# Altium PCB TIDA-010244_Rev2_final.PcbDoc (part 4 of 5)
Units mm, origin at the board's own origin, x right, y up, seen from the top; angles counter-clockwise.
Board outline 155.23 x 187.6 mm, 4 copper layers (GND/Signal 1, Solid GND Layer 1, Solid Power Layer 1, GND/Signal Layer 2), stack 1.59 mm thick; 350 components, 237 nets, 1153 pads, 380 vias.
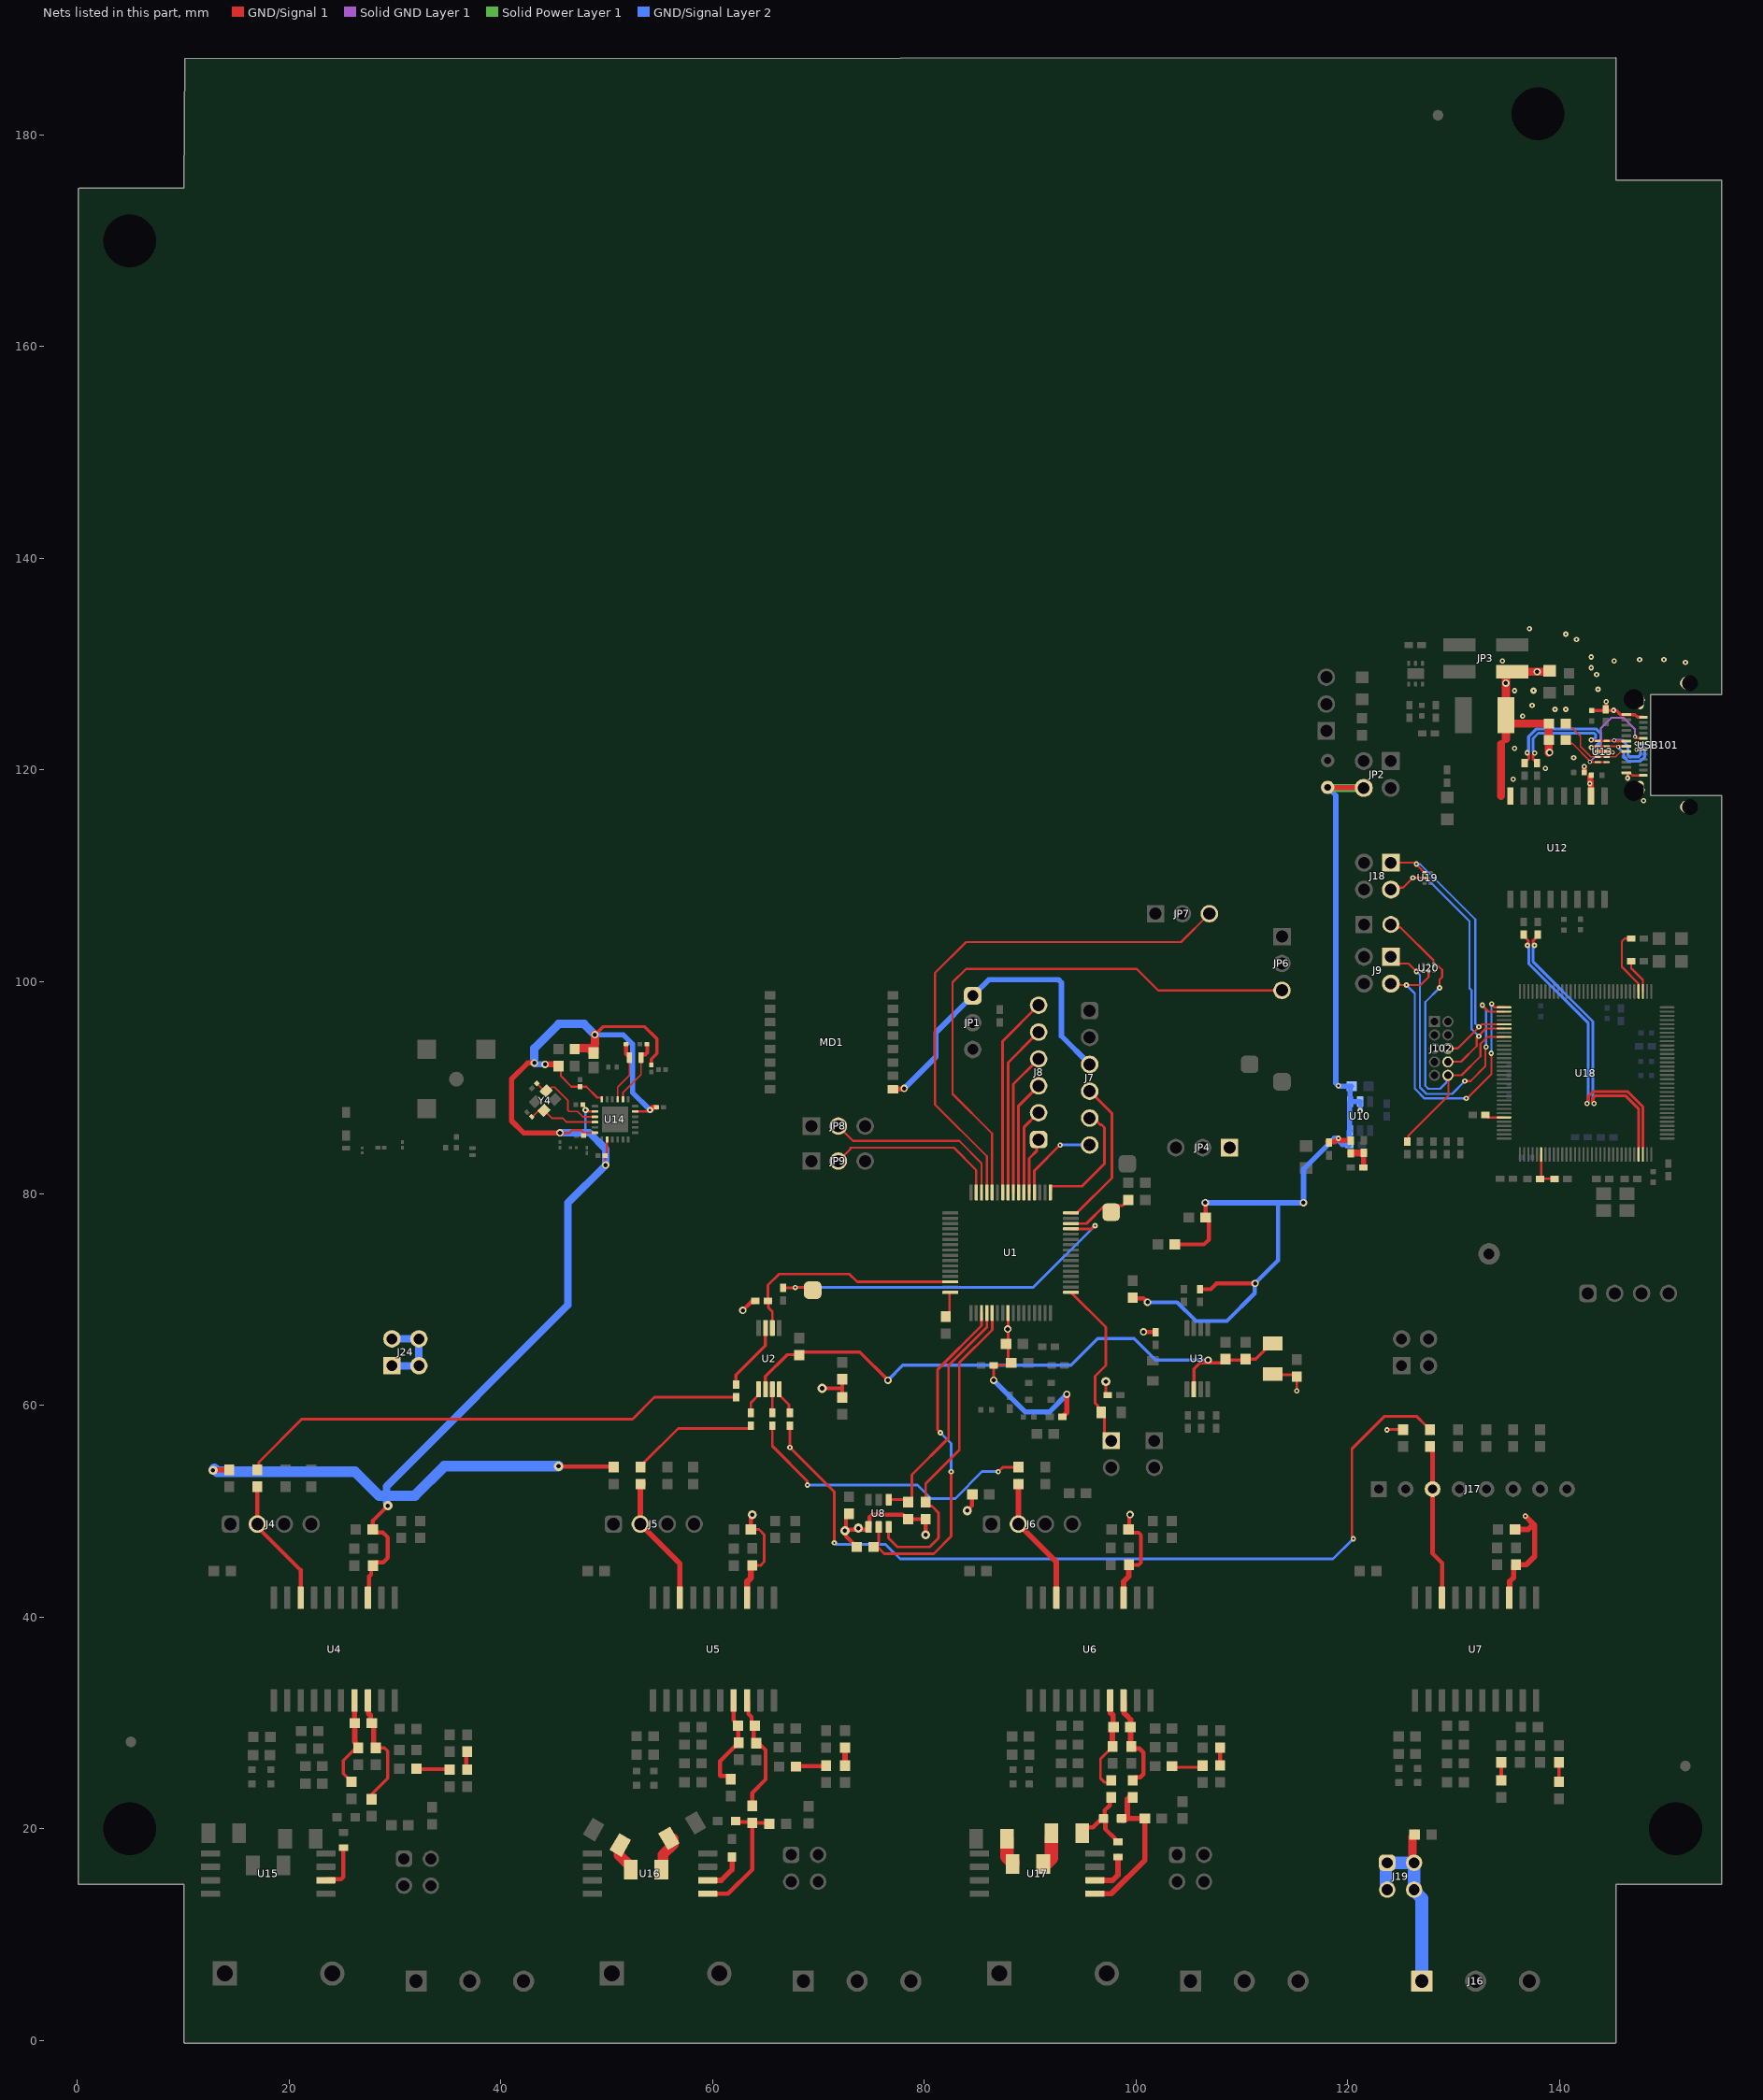
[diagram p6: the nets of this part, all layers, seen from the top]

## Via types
v1: diameter 0.5, hole 0.2, GND/Signal 1 to GND/Signal Layer 2, tented both sides, 236 vias
v2: diameter 0.5, hole 0.2, GND/Signal 1 to GND/Signal Layer 2, 46 vias
v3: diameter 0.864, hole 0.406, GND/Signal 1 to GND/Signal Layer 2, 41 vias
v4: diameter 0.7, hole 0.4, GND/Signal 1 to GND/Signal Layer 2, tented both sides, 40 vias
v5: diameter 0.61, hole 0.203, GND/Signal 1 to GND/Signal Layer 2, tented both sides, 10 vias
v6: diameter 0.4, hole 0.2, GND/Signal 1 to GND/Signal Layer 2, tented both sides, 7 vias

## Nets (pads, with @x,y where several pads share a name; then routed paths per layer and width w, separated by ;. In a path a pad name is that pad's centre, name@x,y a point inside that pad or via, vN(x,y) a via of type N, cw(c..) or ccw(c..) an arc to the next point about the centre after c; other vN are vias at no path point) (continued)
NetR63_1: R63.1 R67.1 R101.2 U16.5 | length 13
  GND/Signal 1 w0.381: U16.5@59.552,13.843 61.468,13.843 63.754,16.129 R67.1@63.754,20.536 ; R63.1@62.191,20.701 62.211,20.682 62.211,20.619 R67.1@63.671,20.619 ; R67.1@63.754,20.574 R67.1@63.754,20.536 ; R101.2@65.374,20.536 R67.1@63.754,20.536 ; R101.2@65.397,20.574 R101.2@65.621,20.574
NetR64_1: R64.1 R65.2 | length 3.1
  GND/Signal 1 w1.016: R64.1@51.435,18.669 51.184,18.418 51.184,17.491 52.271,16.404 R65.2@52.271,16.129
NetR65_1: R65.1 R66.2 | length 3.5
  GND/Signal 1 w1: R65.1@55.171,16.129 55.321,16.279 55.321,17.527 56.318,18.524 56.318,19.044 R66.2@56.275,19.087
NetR68_1: R68.1 R69.2 R72.1 R127.1 | length 7.5
  GND/Signal 1 w0.406: R72.1@94.922,19.558 94.922,19.678 95.369,20.125 95.944,20.125 R69.2@96.647,20.828 ; R69.2@97.028,21.082 97.112,20.998 97.112,19.945 98.051,19.006 98.051,18.881 98.173,18.759 R127.1@98.298,18.759 ; R69.2@97.037,21.082 97.037,21.726 97.515,22.204 97.515,23.093 R68.1@97.536,23.114
NetR69_1: R69.1 R73.1 R103.2 U17.5 | length 14.3
  GND/Signal 1 w0.508: U17.5@96.117,13.843 97.663,13.843 100.838,17.018 R103.2@100.838,20.955 99.187,20.955 99.124,20.892 ; R69.1@98.64,20.955 R69.1@98.787,20.809 ; R69.1@98.933,20.955 99.187,21.209 99.187,22.797 99.441,23.051 R73.1@99.441,23.076
NetR70_1: R70.1 R71.2 | length 2.5
  GND/Signal 1 w1.27: R70.1@87.81,19.05 87.825,19.035 87.825,17.331 R71.2@88.392,16.764
NetR71_1: R71.1 R72.2 | length 2.6
  GND/Signal 1 w1.27: R71.1@91.567,16.764 92.007,17.204 R72.2@92.007,19.162
NetR74_2: R74.2 R75.1 | length 1.9
  GND/Signal 1 w0.381: R75.1@36.703,27.432 36.74,27.395 36.74,25.649 R74.2@36.777,25.612 ; R74.2@36.83,25.565 R74.2@36.872,25.607
NetR76_2: R76.2 R77.1 | length 3.3
  GND/Signal 1 w0.381: R77.1@32.042,25.654 32.087,25.609 35.224,25.609 R76.2@35.306,25.527
NetR78_2: R78.2 R79.1 | length 1.7
  GND/Signal 1 w0.508: R78.2@72.517,25.946 R79.1@72.517,27.648 R79.1@72.517,27.686
NetR80_2: R80.2 R81.1 | length 2.6
  GND/Signal 1 w0.381: R81.1@67.893,25.856 67.938,25.901 70.478,25.901 R80.2@70.485,25.908
NetR82_2: R82.2 R83.1 | length 1.8
  GND/Signal 1 w0.381: R82.2@107.95,25.971 107.95,27.432 R83.1@108.204,27.686
NetR84_2: R84.2 R85.1 | length 3
  GND/Signal 1 w0.254: R85.1@103.302,25.885 103.422,25.765 R85.1@103.655,25.532 ; R85.1@103.422,25.797 103.438,25.781 R84.2@105.918,25.781
NetR92_2: R92.2 R93.1 | length 1.9
  GND/Signal 1 w0.35: R92.2@134.366,24.384 134.493,24.511 R92.2@134.493,24.549 R93.1@134.493,26.251
NetR94_2: R94.2 R95.1 | length 1.9
  GND/Signal 1 w0.35: R94.2@139.827,24.384 139.954,24.511 R95.1@139.954,26.251
NetR119_2: R119.2 U18.3 | length 3.3
  GND/Signal 1 w0.2: R119.2@146.771,101.93 146.771,101.273 147.869,100.175 U18.3@147.869,99.084
NetR120_2: R120.2 U18.4 | length 6.4
  GND/Signal 1 w0.2: R120.2@146.771,104.089 146.165,104.089 145.887,103.811 145.887,101.409 147.469,99.827 U18.4@147.469,99.084
NetR121_1: R121.1 R124.2 U18.70 | length 3.7
  GND/Signal 1 w0.2: U18.70@138.269,83.684 138.269,81.481 R121.1@138.169,81.381 R124.2@139.548,81.381
NetR123_2: R123.2 U15.6 | length 4.6
  GND/Signal 1 w0.381: U15.6@23.484,15.113 23.593,15.222 24.923,15.222 25.146,15.446 R123.2@25.146,18.288
NetR125_2: R125.2 U16.6 | length 3.9
  GND/Signal 1 w0.5: U16.6@59.552,15.113 60.833,15.113 61.849,16.129 R125.2@61.849,17.311
NetR126_2: R126.2 U18.59 | length 1.9
  GND/Signal 1 w0.2: R126.2@133.008,87.411 133.235,87.184 U18.59@134.769,87.184
NetR127_2: R127.2 U17.6 | length 4.2
  GND/Signal 1 w0.508: U17.6@96.117,15.113 97.79,15.113 98.298,15.621 R127.2@98.298,17.38
NEUTRAL: J16.1 J19.1 J19.2 J19.3 J19.4 R106.2 | length 19.2
  GND/Signal 1 w0.762: J19.3@126.111,16.637 126.119,16.645 126.119,17.478 126.111,17.486 126.111,19.24 126.365,19.494 R106.2@126.365,19.525
  GND/Signal Layer 2 w1.2: J19.1@123.571,16.51 123.634,16.447 123.634,14.326 J19.2@123.73,14.23 ; J19.1@123.946,16.77 J19.3@126.27,16.77 ; J19.4@126.238,14.167 127,13.405 J16.1@127,5.588 ; J19.3@126.238,16.891 126.27,16.859 J19.3@126.27,16.77 ; J19.4@126.27,14.23 J19.3@126.27,16.77
PA12: J8.1 U1.5 | length 5.3
  GND/Signal 1 w0.254: U1.5@89.916,80.107 89.916,83.312 90.637,84.033 90.637,84.668 J8.1@90.932,84.963
PA13: J8.2 U1.6 | length 8.2
  GND/Signal 1 w0.254: U1.6@89.416,80.107 89.416,86.241 90.678,87.503 J8.2@90.678,87.757
PA14: J8.3 U1.7 | length 10.7
  GND/Signal 1 w0.254: U1.7@88.916,80.107 88.916,88.281 90.551,89.916 J8.3@90.805,89.916
PA15: J8.4 U1.8 | length 13.2
  GND/Signal 1 w0.254: U1.8@88.416,80.107 88.416,90.321 J8.4@90.551,92.456
PA16: J8.5 U1.9 | length 16.6
  GND/Signal 1 w0.254: U1.9@87.916,80.107 87.916,92.361 90.424,94.869 J8.5@91.186,94.869
PA17: J8.6 U1.10 | length 19.2
  GND/Signal 1 w0.254: U1.10@87.416,80.107 87.416,94.401 J8.6@90.805,97.79 J8.6@90.805,97.917
PWM: pad.3@97.663,78.232 R19.1 U1.62 | length 6.3
  GND/Signal 1 w0.254: U1.62@93.866,77.157 95.318,77.157 97.028,78.867 98.754,78.867 98.903,79.016 98.903,79.027 99.251,79.375 R19.1@99.276,79.375
REACT: D2.1 J3.1 U1.49 | length 16.7
  GND/Signal 1 w0.254: U1.49@93.866,70.657 94.225,70.657 U1.49@94.248,70.634 ; U1.49@93.912,70.611 97.155,67.368 97.155,63.754 96.139,62.738 96.139,60.198 96.39,59.947 96.39,59.632 97.036,58.986 97.036,56.634 J3.1@97.155,56.515
RTS_FTDI: J7.6 U1.4 | length 8.3
  GND/Signal 1 w0.254: U1.4@90.416,80.107 90.416,82.161 v1@92.835,84.58
  GND/Signal Layer 2 w0.254: v1(92.837,84.582) 95.504,84.582 J7.6@95.584,84.662
RXD_FTDI: J7.5 U1.1 | length 11.3
  GND/Signal 1 w0.254: U1.1@91.916,80.107 91.916,80.241 91.939,80.264 91.939,80.68 94.904,80.68 97.028,82.804 97.028,86.233 96.765,86.496 96.635,86.496 96.266,86.865 J7.5@96.266,87.122
SPI_CLK_1: R12.2 R28.2 | length 48.4
  GND/Signal 1 w0.254: R28.2@17.018,53.886 17.153,54.021 17.153,54.618 21.209,58.674 52.451,58.674 54.518,60.741 R12.2@62.23,60.741
SPI_CLK_1_H: J4.2 R28.1 U4.18 | length 12
  GND/Signal 1 w0.381: J4.2@17.018,48.768 R28.1@17.018,52.286 R28.1@17.018,52.324 ; J4.2@17.433,48.675 17.306,48.548 17.306,48.226 21.102,44.43 U4.18@21.102,41.812
SPI_CLK_2: R15.2 R35.2 | length 12.4
  GND/Signal 1 w0.254: R35.2@53.213,54.14 53.561,54.488 53.561,54.607 56.755,57.801 63.454,57.801 63.627,57.974 R15.2@63.627,58.074 R15.2@63.627,58.293
SPI_CLK_2_H: J5.2 R35.1 U5.18 | length 12.2
  GND/Signal 1 w0.508: J5.2@53.188,48.768 53.188,52.299 R35.1@53.467,52.578 ; J5.2@53.34,48.616 56.921,45.034 U5.18@56.921,41.807
SPI_CLK_3: R17.2 R44.2 | length 28.8
  GND/Signal 1 w0.254: R17.2@65.563,58.234 R17.2@65.602,58.194 ; R17.2@65.659,58.074 65.659,56.134 68.959,52.834 68.959,52.453 v1(68.961,52.451) ; v1(86.995,53.721) 87.414,54.14 R44.2@88.9,54.14
  GND/Signal Layer 2 w0.254: v1@68.961,52.473 v1(68.961,52.451) 79.375,52.451 80.645,51.181 82.931,51.181 85.471,53.721 v1(86.995,53.721)
SPI_CLK_3_H: J6.2 R44.1 U6.18 | length 12
  GND/Signal 1 w0.508: R44.1@88.773,52.451 88.9,52.324 J6.2@88.9,48.768 ; J6.2@89.027,48.641 92.481,45.187 U6.18@92.481,41.807
SPI_CLK_4: R13.2 R89.2 | length 81
  GND/Signal 1 w0.254: R13.2@67.31,58.074 v1(67.31,56.007) 71.501,51.816 v1(71.501,46.99) ; v1(120.523,47.371) 120.396,47.498 120.396,55.88 123.444,58.928 126.53,58.928 127.389,58.069 127.414,58.069 127.762,57.721 R89.2@127.762,57.696
  GND/Signal Layer 2 w0.254: v1(71.501,46.99) 71.568,46.99 71.725,46.832 76.358,46.832 77.724,45.466 118.618,45.466 v1(120.523,47.371)
SPI_CLK_4_H: J17.3 R89.1 U7.18 | length 14.2
  GND/Signal 1 w0.406: R89.1@127.889,55.753 128.016,55.626 J17.3@128.016,52.07 ; J17.3@128.016,51.943 128.016,45.974 128.905,45.085 U7.18@128.905,41.807
SPI_CLK_EN: R47.1 U1.30 U2.2 | length 22.2
  GND/Signal 1 w0.254: R47.1@65.243,69.85 65.243,71.339 66.294,72.39 72.927,72.39 73.66,71.657 U1.30@82.466,71.657 ; R47.1@65.278,69.85 65.278,69.215 65.659,68.834 ; U2.2@65.654,67.289 65.654,68.834
SPI_from_Buf_1: R12.1 U2.3 | length 6.5
  GND/Signal 1 w0.305: R12.1@62.23,61.941 62.23,62.865 65.004,65.639 U2.3@65.004,67.289 ; U2.3@65.004,67.289 U2.3@65.024,67.31
SPI_from_Buf_2: R15.1 U2.5 | length 2.5
  GND/Signal 1 w0.254: R15.1@63.754,59.309 63.627,59.436 63.627,60.237 64.354,60.964 U2.5@64.354,61.489
SPI_from_Buf_3: R17.1 U2.7 | length 2.6
  GND/Signal 1 w0.254: R17.1@65.486,59.609 65.486,59.482 R17.1@65.659,59.309 ; U2.7@65.654,61.489 65.656,61.486 65.656,59.439 R17.1@65.786,59.309
SPI_from_Buf_4: R13.1 U2.8 | length 3.1
  GND/Signal 1 w0.254: U2.8@66.304,61.489 66.304,60.964 U2.8@66.35,60.917 ; U2.8@66.35,61.251 U2.8@66.35,60.917 ; R13.1@67.437,59.182 67.213,59.406 67.213,60.055 U2.8@66.35,60.917
SPI_SCK: pad.3@69.469,70.866 R14.1 U1.61 | length 35.9
  GND/Signal 1 w0.254: R14.1@66.675,71.085 v1@67.818,71.085 ; v1(67.818,71.12) pad.3@69.469,71.12 ; U1.61@93.866,76.657 95.767,76.657 96.072,76.962 v1(96.139,76.962)
  GND/Signal Layer 2 w0.254: v1(67.818,71.12) 90.297,71.12 v1(96.139,76.962)
SWCLK: JP7.3 U1.13 | length 51.5
  GND/Signal 1 w0.2: U1.13@85.916,80.107 85.916,83.502 81.026,88.392 81.026,100.838 83.947,103.759 104.267,103.759 JP7.3@106.934,106.426 107.188,106.68 JP7.3@107.315,106.68
SWDIO: JP6.3 U1.12 | length 53.9
  GND/Signal 1 w0.2: U1.12@86.416,80.107 86.416,85.669 82.677,89.408 82.677,99.949 83.947,101.219 100.076,101.219 102.108,99.187 JP6.3@113.792,99.187
TMAG_INT: R98.1 U1.35 U8.5 | length 33.4
  GND/Signal 1 w0.254: R98.1@75.692,46.863 75.349,46.863 76.238,45.974 80.899,45.974 82.55,47.625 v1(82.55,53.721) ; R98.1@75.692,46.99 U8.5@75.692,48.484 ; v1(81.534,57.404) 81.534,57.422 81.28,57.676 81.28,63.373 85.416,67.509 U1.35@85.416,68.707
  GND/Signal Layer 2 w0.254: v1(81.534,57.404) 82.55,56.388 v1(82.55,53.721)
TMAG_SCL: R96.1 U1.36 U8.1 | length 22.9
  GND/Signal 1 w0.254: U8.1@76.642,51.084 78.456,51.084 R96.1@78.594,50.946 ; R96.1@78.676,50.863 78.834,51.021 78.834,53.434 82.296,56.896 82.296,63.754 85.916,67.374 U1.36@85.916,68.707
TMAG_SDA: R97.1 U1.37 U8.6 | length 30.9
  GND/Signal 1 w0.254: U8.6@76.581,48.387 76.642,48.326 76.642,47.437 77.47,46.609 80.518,46.609 81.361,47.452 81.361,49.83 80.726,50.465 80.485,50.465 80.137,50.813 80.137,52.578 83.312,55.753 83.312,64.008 86.416,67.112 U1.37@86.416,68.707
TXD_FTDI: J7.4 U1.64 | length 13.8
  GND/Signal 1 w0.254: U1.64@93.866,78.157 94.466,78.157 94.489,78.18 94.489,78.233 97.716,81.46 97.716,87.577 96.087,89.206 96.087,89.229 J7.4@96.139,89.281
UART_RX_to_BLE: JP9.2 U1.15 | length 16.6
  GND/Signal 1 w0.2: JP9.2@71.882,83.058 73.025,84.201 73.025,84.328 82.804,84.328 84.916,82.216 U1.15@84.916,80.107
UART_TX_to_BLE: JP8.2 U1.14 | length 18.3
  GND/Signal 1 w0.2: JP8.2@71.374,86.614 71.628,86.614 JP8.2@71.882,86.36 73.279,84.963 83.312,84.963 85.416,82.859 U1.14@85.416,80.107
USB_CC1: R54.2 U13.4 U13.7 USB101.A5 | length 7.6
  GND/Signal 1 w0.152: R54.2@140.599,124.4 140.997,124.001 141.175,124.001 141.986,123.19 141.986,122.217 142.957,121.246 U13.4@143.633,121.246 U13.7@144.468,121.246 145.309,121.246 145.784,121.721 USB101.A5@146.119,121.721
USB_CC2: R55.2 U13.5 U13.6 USB101.B5 | length 14
  GND/Signal 1 w0.152: R55.2@140.715,122.914 140.715,122.823 141.022,122.516 141.238,122.516 142.926,120.828 v6@142.957,120.797 ; v6(142.875,120.777) 142.906,120.746 U13.5@143.633,120.746 U13.6@144.468,120.746
  GND/Signal 1 w0.2: v6(147.132,123.135) 147.273,122.994 USB101.B5@147.919,122.994
  Solid GND Layer 1 w0.2: v6(142.875,120.777) 143.903,121.805 143.903,123.951 144.894,124.941 146.047,124.941 147.132,123.856 v6(147.132,123.135)
USB_DM: R50.1 U13.1 U13.10 USB101.A7 USB101.B7 | length 18.2
  GND/Signal 1 w0.2: v1@143.002,122.936 143.002,122.93 143.186,122.746 U13.1@143.633,122.746 ; U13.1@143.7,122.746 U13.10@144.468,122.746 145.044,122.746 145.107,122.809 v6(145.161,122.809)
  GND/Signal 1 w0.22: v6@147.32,121.92 147.325,121.92 147.375,121.969 147.894,121.969 USB101.B7@147.919,121.994
  GND/Signal 1 w0.27: v1(137.666,121.597) 137.517,121.449 137.517,121.014 R50.1@137.877,120.654 ; v6(145.161,122.809) 145.196,122.809 145.261,122.744 USB101.A7@146.319,122.744
  GND/Signal Layer 2 w0.27: v1@137.508,121.755 v1(137.666,121.597) ; v1@137.508,121.771 137.508,122.987 137.999,123.478 143.277,123.478 143.435,123.32 143.435,123.096 143.233,122.894 143.045,122.894 v1(143.001,122.85) ; v6(145.161,122.809) 145.186,122.834 145.625,122.834 145.631,122.84 145.901,122.84 146.472,122.269 146.472,121.44 146.658,121.254 147.464,121.254 147.647,121.437 147.647,121.9 147.538,122.009 147.366,122.009 v6(147.264,121.907)
USB_DP: R52.1 U13.2 U13.9 USB101.A6 USB101.B6 | length 21.3
  GND/Signal 1 w0.2: v1@143.023,122.126 143.085,122.126 143.206,122.246 U13.2@143.633,122.246 ; U13.2@143.692,122.246 U13.9@144.468,122.246 145.416,122.246 145.488,122.174 v6(145.542,122.174)
  GND/Signal 1 w0.22: v6@147.193,122.555 147.254,122.494 USB101.B6@147.919,122.494
  GND/Signal 1 w0.27: R52.1@136.7,120.654 137.097,121.052 137.097,121.484 v1(136.949,121.632) ; v6(145.542,122.174) 145.577,122.174 145.647,122.244 USB101.A6@146.319,122.244
  GND/Signal Layer 2 w0.27: v1(136.949,121.632) 137.088,121.771 137.088,123.161 137.825,123.898 143.451,123.898 143.895,123.454 143.895,122.716 143.357,122.178 143.056,122.178 v1(143.014,122.135) ; v6(145.542,122.174) 145.542,122.147 146.052,121.637 146.052,121.266 146.484,120.834 147.638,120.834 148.067,121.263 148.067,122.074 147.712,122.429 147.361,122.429 v6(147.276,122.514)
USB_GND: C16.1 C44.1 C47.2 C101.1 JP3.3 LED7.1 R48.1 R54.1 R55.1 U12.2 U12.8 U13.3@143.633,121.746 U13.8@144.468,121.746 USB101.1 USB101.2 USB101.3 USB101.4 USB101.A1 USB101.A12 USB101.B1 USB101.B12 | length 33.4
  GND/Signal 1 w0.22: USB101.A1@146.319,119.744 146.406,119.744 146.431,119.719 v1(146.431,119.253) ; USB101.A1@146.558,119.761 146.617,119.761 146.884,119.494 USB101.B12@147.919,119.494
  GND/Signal 1 w0.3: C44.1@142.336,119.792 C44.1@142.392,119.736 ; C101.1@143.048,125.638 145.366,125.638 145.76,125.244 USB101.A12@146.319,125.244 147.118,125.244 147.368,124.994 USB101.B1@147.919,124.994 ; U13.3@143.695,121.741 144.547,121.741 144.592,121.696 144.977,121.696 145.007,121.666 v6(145.034,121.666) ; R48.1@144.374,125.736 144.404,125.766 v1(144.404,126.454)
  GND/Signal 1 w0.5: C44.1@142.336,119.792 v1(142.336,120.327) ; v1@142.875,118.717 142.875,119.373 C16.1@143.005,119.503 ; U12.2@142.977,117.538 142.977,118.985
  GND/Signal 1 w0.762: 134.468,117.538 134.468,122.461 ; 134.944,122.937 C47.2@134.944,125.171 134.944,128.709 JP3.3@135.52,129.285 LED7.1@139.138,129.285 ; C47.2@135.715,124.4 R54.1@138.999,124.4 R55.1@138.999,122.851 v4@138.999,121.609
  other v1: 147.955,117.094 142.858,118.717 135.636,119.126 138.684,120.142 135.763,122.047 136.525,125.095 145.108,125.65 135.763,127.508 143.002,129.667 134.62,130.302
  other v2: 141.351,121.158 139.573,125.73 140.589,125.73 137.414,126.111 143.637,127.635 143.51,129.032 151.892,130.175 145.161,130.302 147.574,130.429 149.86,130.429 143.002,130.683 141.605,132.334 140.589,132.842 137.16,133.35
  other v4: 139.065,121.666 134.93,128.223 137.899,129.289
  other v5: 137.541,127.508
V_Phase_A_N: C50.1 C51.1 R56.2 U4.7 | length 8.4
  GND/Signal 1 w0.3: R56.2@25.908,24.422 25.908,24.447 25.146,25.209 25.146,26.416 C50.1@26.162,27.432
  GND/Signal 1 w0.508: C51.1@26.187,29.972 U4.7@26.187,32.107 ; C51.1@26.213,29.972 26.213,28.179 26.322,28.07 26.322,27.881 26.543,27.66 C50.1@26.543,27.635
V_Phase_A_P: C51.2 C52.2 R61.2 U4.8 | length 11.1
  GND/Signal 1 w0.3: R61.2@27.813,22.86 27.813,23.241 29.337,24.765 29.337,27.305 29.007,27.635 C52.2@28.194,27.635
  GND/Signal 1 w0.5: U4.8@27.457,32.107 27.507,32.057 27.507,30.876 27.686,30.697 27.686,30.099 C51.2@27.813,29.972 28.003,29.781 28.003,27.885 C52.2@28.203,27.686
V_Phase_B_N: C53.1 C54.1 R62.2 U5.7 | length 9.7
  GND/Signal 1 w0.381: R62.2@61.468,24.511 61.468,24.955 61.437,24.985 60.74,24.985 60.706,25.019 60.706,26.365 62.137,27.795 62.199,27.795 62.446,28.042 62.446,29.68 C54.1@62.408,29.718 62.383,29.718 62.098,30.003 62.098,30.129 62.001,30.226 U5.7@62.001,32.107 ; R62.2@61.722,24.676 61.722,24.669 R62.2@62.007,24.384
V_Phase_B_P: C54.2 C55.2 R67.2 U5.8 | length 11.7
  GND/Signal 1 w0.381: U5.8@63.271,32.107 63.381,31.998 63.381,30.853 63.698,30.536 63.698,29.647 C54.2@63.817,29.527 ; R67.2@63.881,22.098 63.754,22.225 63.754,23.368 65.024,24.638 65.024,27.432 64.534,27.922 C55.2@64.039,27.922 ; C55.2@64.008,28.067 63.881,28.194 63.881,29.591 C54.2@64.008,29.718
V_Phase_C_N: C56.1 C57.1 R68.2 U6.7 | length 8.9
  GND/Signal 1 w0.25: R68.2@97.282,24.384 97.255,24.357 97.047,24.357 96.647,24.757 96.647,26.594 97.79,27.737 C56.1@97.79,27.762
  GND/Signal 1 w0.406: R68.2@97.663,24.402 R68.2@97.681,24.384 ; R68.2@97.917,24.275 R68.2@97.917,24.638
  GND/Signal 1 w0.508: U6.7@97.561,32.107 97.607,32.061 97.607,30.917 97.79,30.734 ; C56.1@97.771,27.921 97.771,29.483 C57.1@97.879,29.591 ; C57.1@97.847,29.648 97.847,30.734
V_Phase_C_P: C57.2 C58.2 R73.2 U6.8 | length 9
  GND/Signal 1 w0.406: C58.2@99.568,27.742 C58.2@99.568,27.762 ; C58.2@99.695,27.831 99.967,27.559 100.33,27.559 100.457,27.432 100.711,27.178 100.711,25.146 100.411,24.846 99.967,24.846 99.822,24.701 R73.2@99.822,24.511
  GND/Signal 1 w0.508: U6.8@98.831,32.107 98.877,32.061 98.877,30.917 99.06,30.734 ; 99.131,30.663 99.504,30.29 99.504,29.591 C58.2@99.504,27.851
VCORE: C2.2 U1.32 | length 2.6
  GND/Signal 1 w0.254: C2.2@81.915,68.453 82.106,68.453 82.39,68.737 82.39,70.634 82.413,70.657 U1.32@82.466,70.657
VDD_3V3: C1.1 C3.2 C6.2 C15.1 C25.2 C26.1 C33.2 C34.1 C36.2 C37.1 C78.1 C79.2 C80.1 C105.2 C106.2 C107.2 C108.2 C110.2 C111.2 C112.1 C120.2 C121.1 J7.3 J24.1 J24.2 J24.3 J24.4 JP1.1 JP2.4 JP4.1 L1.1 L3.1 MD1.9 R1.2 R2.2 R3.2 R4.2 R6.2 R7.2 R8.2 R24.2 R25.2 R31.2 R36.2 R39.2 R42.2 R47.2 R96.2 R97.2 R98.2 R99.2 R109.2 R122.1 TP4.1 U1.40 U4.13 U5.13 U6.13 U7.13 U8.4 U10.3 U10.4 U10.5 U14.2 U14.11 U14.18 U14.20 U14.24 | length 382.3
  GND/Signal 1 w0.2: C108.2@45.466,92.037 45.679,91.824 45.679,91.1 46.685,90.094 C106.2@47.422,90.094 ; v4@45.72,85.725 46.482,85.725 46.736,85.979 ; 46.736,85.985 47.597,85.985 47.828,85.754 47.828,85.745 ; C106.2@47.498,90.094 48.082,90.094 49.125,89.051 49.525,89.051 49.53,89.046 U14.18@49.53,88.9 ; C111.2@47.625,88.502 47.735,88.392 C111.2@47.752,88.392 47.769,88.392 47.879,88.282 47.879,88.011 v5(48.006,87.884) 48.145,87.745 U14.20@48.9,87.745 ; C107.2@47.828,85.598 47.828,85.745 ; U14.24@48.9,85.745 47.828,85.745 ; v4(49.911,82.677) 49.886,82.702 49.886,83.541 C110.2@49.911,83.566 ; C110.2@49.911,83.693 50.038,83.82 50.038,85.083 U14.2@50.05,85.095
  GND/Signal 1 w0.25: U14.11@52.7,87.745 53.866,87.745 54.005,87.884 v5(54.102,87.884)
  GND/Signal 1 w0.254: U4.13@27.452,41.812 U4.13@27.564,41.924 ; C34.1@63.754,44.869 64.554,44.869 64.897,45.212 64.897,47.752 64.389,48.26 C33.2@63.881,48.26 ; v4(86.56,62.357) 86.56,63.735 86.604,63.779 87.998,63.779 C3.2@88.227,64.008 87.916,64.319 U1.40@87.916,68.707 ; v3(97.155,62.23) 97.155,61.041 R2.2@97.236,60.96 ; L1.1@113.03,62.865 115.024,62.865 C15.1@115.189,62.7 v1(115.189,61.341) ; C15.1@115.432,62.534 C15.1@115.514,62.616 ; v1(123.698,57.658) 123.736,57.696 R99.2@125.222,57.696
  GND/Signal 1 w0.3: v4(48.895,94.996) 49.657,95.758 53.594,95.758 54.737,94.615 54.737,93.218 54.229,92.71 R122.1@54.229,92.151
  GND/Signal 1 w0.35: C36.2@99.187,48.26 99.487,47.96 100.249,47.96 100.457,47.752 100.457,45.125 100.252,44.92 C37.1@99.339,44.92 ; C36.2@99.301,48.26 99.374,48.333 99.374,49.59 v4(99.441,49.657)
  GND/Signal 1 w0.381: U4.13@27.562,41.924 27.562,42.892 27.564,42.895 27.564,43.82 27.758,44.014 C25.2@27.758,44.671 ; C26.1@27.927,48.26 27.927,49.093 v3(29.337,50.503) ; C25.2@27.94,44.844 27.94,44.869 28.225,45.153 28.897,45.153 29.337,45.593 29.337,47.498 28.86,47.975 28.098,47.975 C26.1@27.94,48.133 ; v3(45.466,54.229) 45.511,54.184 50.591,54.184 R39.2@50.673,54.102 ; v4(62.865,68.961) 63.645,69.741 63.933,69.741 R47.2@64.043,69.85 ; C33.2@63.64,48.26 63.64,49.256 63.881,49.498 v3@63.881,49.53 ; v3(70.358,61.595) 72.263,61.595 ; C79.2@72.263,60.744 72.263,61.595 ; C79.2@72.517,60.821 C79.2@72.548,60.852 ; C80.1@72.517,62.357 72.484,62.357 72.263,62.136 72.263,61.595 ; v3@72.644,48.26 72.609,48.295 72.609,49.33 C78.1@72.771,49.492 ; R96.2@78.105,49.53 77.978,49.657 75.075,49.657 74.851,49.434 74.851,48.593 U8.4@74.742,48.484 74.742,48.335 74.632,48.225 72.609,48.225 v3(72.517,48.133) 72.609,48.041 72.609,47.622 73.313,46.919 73.313,46.894 R98.2@73.597,46.609 ; R96.2@78.486,49.149 78.575,49.238 R97.2@80.137,49.238 80.137,47.975 80.041,47.879 v3@80.01,47.879 ; v3(84.074,50.038) 84.074,50.07 84.519,50.515 84.519,51.537 R42.2@84.544,51.562 ; R24.2@99.568,70.104 100.711,70.104 v4(101.092,69.723) ; v4(100.711,66.929) 100.728,66.912 101.836,66.912 R1.2@101.854,66.894 ; R25.2@103.67,75.184 106.426,75.184 106.9,75.658 106.9,77.47 106.68,77.69 R31.2@106.68,77.851 ; R7.2@106.045,70.958 107.067,70.958 107.61,71.501 v4(111.252,71.501) ; v4(106.553,79.121) 106.572,79.102 R31.2@106.572,77.851 ; R98.2@73.597,46.609 R98.2@73.622,46.609 R98.2@73.597,46.609
  GND/Signal 1 w0.5: v4(43.18,92.329) 42.545,92.329 41.021,90.805 41.021,86.868 42.164,85.725 v4(45.593,85.725) ; v5(54.102,87.884) 54.132,87.884 54.386,88.138 C105.2@54.712,88.138 ; MD1.9@77.047,89.838 77.087,89.878 78.067,89.878 v4(78.105,89.916) ; R8.2@93.102,58.936 93.456,59.29 93.456,59.569 93.47,59.583 v4@93.47,61.043 ; R109.2@118.11,84.887 118.796,84.887 v1(119.126,85.217) 119.337,85.006 R4.2@120.292,85.006 ; TP4.1@118.11,118.364 118.135,118.339 121.183,118.339 JP2.4@121.285,118.237 ; JP2.4@121.482,118.281 JP2.4@121.514,118.313
  GND/Signal 1 w0.508: v3@12.872,53.886 R36.2@14.351,53.886 ; U6.13@98.831,41.807 98.831,43.332 99.314,43.815 C37.1@99.314,44.704 ; U7.13@135.255,41.807 135.301,41.853 135.301,43.353 135.669,43.721 C121.1@135.669,44.864 ; C120.2@135.801,48.26 137.033,48.26 137.414,48.641 ; C121.1@135.89,44.92 136.868,44.92 137.668,45.72 137.668,48.641 v1(136.779,49.53)
  GND/Signal 1 w0.6: v4(44.196,92.202) 45.301,92.202 C108.2@45.466,92.037 ; v4(45.593,85.725) v4@45.72,85.725 ; U5.13@63.271,41.807 63.271,43.332 63.627,43.688 C34.1@63.627,44.831
  GND/Signal 1 w0.8: C112.1@47.117,93.726 48.301,93.726 48.615,93.412 48.689,93.412 48.768,93.333 L3.1@48.768,93.259 48.847,93.338 48.847,94.09 48.895,94.138 v4(48.895,94.996)
  Solid Power Layer 1 w0.762: TP4.1@118.237,118.237 118.313,118.313 JP2.4@121.514,118.313
  GND/Signal Layer 2 w0.2: v4(45.593,85.725) 45.689,85.821 48.006,85.821 v5(48.006,87.884)
  GND/Signal Layer 2 w0.381: v4(101.092,69.723) 103.886,69.723 105.664,67.945 108.585,67.945 111.219,70.579 111.219,71.468 113.411,73.66 113.411,79.121
  GND/Signal Layer 2 w0.4: v1(121.169,87.811) 121.173,87.816 U10.5@121.173,88.661
  GND/Signal Layer 2 w0.5: v4(48.895,94.996) 51.562,94.996 52.451,94.107 52.451,89.535 v5(54.102,87.884) ; v4(78.105,89.916) 81.106,92.917 81.106,95.203 JP1.1@84.582,98.679 86.106,100.203 92.671,100.203 92.964,99.91 92.964,94.869 J7.3@95.631,92.202 ; v4(86.56,62.357) 89.561,59.356 91.805,59.356 v4(93.472,61.022) ; v4@106.426,79.121 v4(106.553,79.121) v4(115.824,79.121) 115.824,82.296 118.745,85.217 v1(119.126,85.217) 119.126,85.01 119.492,84.644 120.094,84.644 C6.2@120.142,84.595 120.142,85.86 U10.3@120.219,85.936 ; TP4.1@118.11,118.364 118.872,117.602 118.872,90.424 119.157,90.139 R6.2@120.369,90.139 120.219,89.989 U10.4@120.219,88.686 ; U10.3@120.184,85.971 120.184,88.651 U10.4@120.219,88.686 ; U10.5@121.169,88.686 U10.4@120.219,88.686
  GND/Signal Layer 2 w0.6: v4@43.307,92.202 v4(44.196,92.202)
  GND/Signal Layer 2 w0.7: v3(29.337,50.503) 29.306,50.534 29.306,50.704 29.21,50.8 29.21,51.435 29.21,52.324 46.355,69.469 46.355,79.121 v4(49.911,82.677) 49.911,84.201 48.387,85.725 v4(45.593,85.725) ; J24.1@29.464,64.008 29.742,63.73 J24.3@32.27,63.73 ; J24.2@29.869,66.27 J24.4@32.27,66.27 J24.3@32.27,63.893
  GND/Signal Layer 2 w0.8: 43.18,92.71 43.18,93.726 45.466,96.012 47.879,96.012 v4(48.895,94.996)
  GND/Signal Layer 2 w1: v3@12.954,53.975 13.208,53.721 26.226,53.721 28.511,51.435 29.21,51.435 31.877,51.435 34.671,54.229 v3(45.466,54.229)
  other v1: 119.126,90.17
  other v3: 80.137,47.752 73.787,48.387 63.754,49.657 12.827,53.848
  other v4: 87.884,67.183
VDDO_IN_1: C9.1 C13.2 C14.2 L1.2 U2.6 U3.6 | length 57.2
  GND/Signal 1 w0.305: U2.6@65.024,61.722 65.004,61.742 65.004,62.718 67.056,64.77 C14.2@68.199,64.77 ; C14.2@68.199,64.732 68.491,65.024 73.914,65.024 v4(76.581,62.357) ; U3.6@105.466,61.489 105.466,63.429 106.04,64.003 108.135,64.003 C13.2@108.47,64.338 ; C13.2@108.585,64.262 110.274,64.262 C9.1@110.363,64.351 111.295,64.351 112.13,65.186 112.13,65.341 112.194,65.405 L1.2@112.522,65.405
  GND/Signal Layer 2 w0.305: v4(76.581,62.357) 77.989,63.765 93.853,63.765 96.383,66.294 99.822,66.294 101.854,64.262 v4(106.807,64.262)
X32_N: C102.2 U14.15 Y3.2 | length 5.2
  GND/Signal 1 w0.16: U14.15@51.05,88.895 51.05,90.039 52.155,91.144 52.155,92.498 Y3.2@52.07,92.583
  GND/Signal 1 w0.381: C102.2@51.842,94.107 51.842,93.192 Y3.2@51.943,93.091
X32_P: C103.1 U14.14 Y3.1 | length 6
  GND/Signal 1 w0.16: U14.14@51.55,88.895 51.55,89.523 53.255,91.228 Y3.1@53.255,92.668
  GND/Signal 1 w0.381: Y3.1@53.255,93.087 53.314,93.147 53.68,93.147 53.848,93.314 C103.1@53.848,94.107
X48_N: C4.2 U14.22 Y4.1 | length 6.7
  GND/Signal 1 w0.16: C4.2@42.926,87.249 42.998,87.249 43.633,87.884 Y4.1@44.069,87.884 ; Y4.1@44.196,87.884 44.196,87.757 44.831,87.122 45.847,87.122 46.224,86.745 U14.22@48.9,86.745
X48_P: C81.1 U14.21 Y4.3 | length 7.6
  GND/Signal 1 w0.16: C81.1@43.413,90.403 44.155,89.662 Y4.3@44.302,89.662 ; Y4.3@44.302,89.692 44.48,89.692 44.831,90.043 45.085,90.043 46.355,88.773 46.355,87.851 46.449,87.757 47.244,87.757 47.756,87.245 48.891,87.245 U14.21@48.895,87.249
XDS_DM: R51.2 U18.93 | length 28
  GND/Signal 1 w0.27: v1(137.631,103.446) 137.487,103.59 137.487,103.862 137.944,104.318 R51.2@137.944,104.451 ; v1@143.339,88.469 143.136,88.672 143.136,88.986 143.359,89.209 146.279,89.209 147.465,88.023 U18.93@147.465,84.346
  GND/Signal Layer 2 w0.2: v1@137.631,103.327 137.571,103.387 137.543,103.415 137.574,103.446 v1(137.631,103.446)
  GND/Signal Layer 2 w0.27: v1(137.631,103.446) 137.571,103.387 137.515,103.331 137.515,101.887 143.149,96.253 143.149,88.619 v1(143.259,88.509)
XDS_DP: R53.2 U18.94 | length 29.2
  GND/Signal 1 w0.27: R53.2@136.611,104.451 136.611,104.336 137.067,103.88 137.067,103.505 v1@136.981,103.419 ; v1@142.559,88.449 142.716,88.606 142.716,89.16 143.185,89.629 146.453,89.629 147.885,88.197 U18.94@147.885,84.325
  GND/Signal Layer 2 w0.27: v1@136.981,103.419 137.095,103.304 137.095,101.713 142.729,96.079 142.729,88.629 v1(142.609,88.509)
  other v1: 136.981,103.446
XDS_RESET_OUT: J2.2 J102.10 R118.1 U18.40 U20.1 | length 37.2
  GND/Signal 1 w0.2: J2.2@123.456,105.15 J2.2@123.704,105.15 ; J2.2@124.079,105.41 124.339,105.15 124.974,105.15 128.102,102.022 128.102,101.631 U20.1@128.14,101.593 128.437,101.593 128.912,101.117 128.912,100.435 128.674,100.197 v1(128.674,99.419) ; R118.1@125.623,84.891 125.733,85.002 125.733,85.474 129.507,89.248 J102.10@129.507,91.16 ; J102.10@129.469,91.162 130.754,91.162 132.544,92.951 132.544,94.134 133.194,94.784 U18.40@134.769,94.784
  GND/Signal Layer 2 w0.2: v1(128.674,99.419) 127.331,98.075 127.331,91.908 127.331,90.167 127.611,89.887 128.715,89.887 129.344,90.516 129.344,91.037 J102.10@129.467,91.16
XDS_RXD: J9.3 U18.33 U20.5 | length 31
  GND/Signal 1 w0.2: J9.3@124.079,99.822 124.213,99.688 126.866,99.688 126.873,99.695 ; 126.88,99.688 127.64,100.448 U20.5@127.64,101.018 ; v1(131.191,88.974) 131.26,88.974 133.567,91.28 v1@133.567,93.247 ; v1@133.604,97.79 133.631,97.79 133.837,97.584 U18.33@134.769,97.584
  GND/Signal Layer 2 w0.2: v1(125.538,99.688) 126.328,98.897 126.328,89.901 127.256,88.974 v1(131.191,88.974) ; v1(133.563,93.247) 133.583,93.268 133.583,97.769 v1@133.604,97.79
  other v1: 133.604,97.917
XDS_TDI: J18.3 J102.8 U18.38 U19.5 | length 29.1
  GND/Signal 1 w0.2: J18.3@124.079,108.458 124.512,108.891 125.229,108.891 v1(126.165,109.826) ; v1@126.2,109.817 127.249,109.817 U19.5@127.264,109.802 ; J102.8@129.47,92.442 130.707,92.442 132.19,93.924 132.19,94.718 133.056,95.584 U18.38@134.769,95.584
  GND/Signal Layer 2 w0.2: v1(126.165,109.826) 127.396,109.826 131.501,105.72 131.501,99.385 131.699,99.187 131.699,95.53 ; 131.699,95.504 131.699,95.53 ; v1(132.377,94.852) 131.699,95.53
XDS_TDO_SWO: J18.1 J102.6 U18.37 U19.4 | length 28.1
  GND/Signal 1 w0.2: J18.1@123.825,111.252 J18.1@124.079,111.252 126.314,111.252 127.164,110.402 127.164,110.352 127.214,110.302 U19.4@127.264,110.302 ; J102.6@129.467,93.7 130.394,93.7 132.401,95.706 132.679,95.984 U18.37@134.769,95.984
  GND/Signal Layer 2 w0.2: v1(126.492,111.125) 126.513,111.104 126.849,111.104 132.063,105.889 132.063,96.043 v1(132.377,95.73)
XDS_TXD: J9.1 U18.34 U20.4 | length 30.3
  GND/Signal 1 w0.2: J9.1@124.206,102.235 124.714,101.727 125.73,101.727 v1(126.492,100.965) 126.519,100.992 127.09,100.992 U20.4@127.09,101.041 ; v1(131.061,90.608) 131.08,90.627 131.611,90.627 133.005,92.02 v1@133.005,93.877 ; v1(132.715,97.79) 133.321,97.184 U18.34@134.769,97.184
  GND/Signal Layer 2 w0.2: v1(126.492,100.965) 126.827,100.63 126.827,90.029 127.448,89.408 129.862,89.408 v1(131.061,90.608) ; v1(132.715,97.79) 132.715,97.733 133.076,97.373 v1(133.076,93.84)
XRSn: C7.1 R4.1 R5.2 | length 2.6
  GND/Signal 1 w0.15: R5.2@121.533,83.814 R5.2@121.539,83.82
  GND/Signal 1 w0.5: R5.2@121.514,83.834 121.496,83.817 121.496,82.466 C7.1@121.539,82.423
  GND/Signal 1 w0.7: R4.1@120.292,83.806 120.306,83.82 R5.2@121.464,83.82
pads on no net: D6.1S D6.2S FID1.1 FID2.1 FID3.1 H1. H2. H3. H4. LBL1.0 MD1.1 MD1.14 MD1.15 U1.2 U1.16 U1.17 U1.18 U1.20 U1.21 U1.22 U1.24 U1.25 U1.27 U1.28 U1.29 U1.33 U1.34 U1.39 U1.42 U1.43 U1.44 U1.48 U1.57 U13.3@143.633,121.746 U13.8@144.468,121.746 U15.1 U15.2 U15.3 U15.7 U15.8 U16.1 U16.2 U16.3 U16.7 U16.8 U17.1 U17.2 U17.3 U17.7 U17.8 U18.1 U18.2 U18.5 U18.6 U18.11 U18.12 U18.13 U18.14 U18.15 U18.18 U18.19 U18.20 U18.21 U18.22 U18.23 U18.24 U18.25 U18.27 U18.29 U18.30 U18.31 U18.32 U18.41 U18.42 U18.43 U18.44 U18.45 U18.46 U18.49 U18.50 U18.53 U18.54 U18.56 U18.57 U18.65 U18.67 U18.71 U18.72 U18.73 U18.74 U18.75 U18.76 U18.77 U18.78 U18.81 U18.82 U18.83 U18.84 U18.85 U18.86 U18.91 U18.92 U18.95 U18.102 U18.103 U18.104 U18.105 U18.106 U18.107 U18.108 U18.109 U18.110 U18.111 U18.112 U18.116 U18.117 U18.118 U18.119 U18.120 U18.121 U18.123 U18.124 U18.125 U18.126 U18.127 U18.128 U20.2 U101.5 U101.7@125.959,129.108 U101.7@126.859,129.108 USB101.A2 USB101.A3 USB101.A8 USB101.A10 USB101.A11 USB101.B2 USB101.B3 USB101.B8 USB101.B10 USB101.B11

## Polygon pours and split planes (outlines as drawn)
GND on GND/Signal 1 "GND/SIGNAL_1_GND_P073" (solid, remove dead copper, pour order 73): 116.265,133.076 116.223,109.662 116.258,98.013 25.76,97.822 25.76,61.281 11.388,61.281 11.388,43.502 153.991,43.502 153.991,105.02 132.186,105.02 132.186,133.001
USB_GND on GND/Signal 1 "Top Signal-USB_GND" (solid, remove dead copper, pour order 81): 134.167,134.821 134.167,116.967 147.35,116.991 150.451,115.901 153.956,115.901 153.956,133.764 153.882,133.764 152.825,134.821
HGND_C_FB on GND/Signal 1 "GND/SIGNAL_1_HGND_C_FB_P060" (solid, remove dead copper, pour order 60): 90.932,22.352 90.932,28.194 105.156,28.194 105.156,22.352
HGND_A_FB on GND/Signal 1 "GND/SIGNAL_1_HGND_A_FB_P051" (solid, remove dead copper, pour order 51): 19.431,23.749 19.431,28.321 34.163,28.321 34.163,23.749
HGND_B_FB on GND/Signal 1 "GND/SIGNAL_1_HGND_B_FB_P049" (solid, remove dead copper, pour order 49): 55.245,22.098 55.245,28.321 69.85,28.321 69.85,22.098
VDD_3V3 on GND/Signal 1 "GND/SIGNAL_1_VDD_3V3_P092" (solid, remove dead copper, pour order 92): 46.482,96.393 46.482,93.091 46.863,92.71 49.657,92.71 49.657,96.393
HGND_D_FB on GND/Signal 1 "GND/SIGNAL_1_HGND_D_FB_P087" (solid, remove dead copper, pour order 87): 126.365,21.971 126.365,28.702 138.049,28.702 138.049,21.971
GND on Solid GND Layer 1 "SOLID_GND_LAYER_1_GND_P062" (solid, remove dead copper, pour order 62): 112.776,108.054 112.776,98.791 50.004,98.791 50.004,60.436 12.433,60.535 12.433,22.964 154.271,22.964 153.763,108.054
USB_GND on Solid GND Layer 1 "Top Signal-USB_GND" (solid, remove dead copper, pour order 83): 134.167,134.694 134.167,114.672 134.516,114.324 153.956,114.324 153.956,133.637 153.882,133.637 152.825,134.694
USB_GND on Solid Power Layer 1 "Top Signal-USB_GND" (solid, remove dead copper, pour order 84): 134.04,134.694 134.04,114.672 134.389,114.324 153.829,114.324 153.829,133.637 153.755,133.637 152.698,134.694
VDD_3V3 on Solid Power Layer 1 "SOLID_POWER_LAYER_1_VDD_3V3_P072" (solid, remove dead copper, pour order 72): 27.02,47.879 27.02,68.717 50.165,68.717 50.165,97.536 82.042,97.536 117.221,97.536 117.221,62.103 137.033,62.103 137.033,47.879
+3V3_XDS110 on Solid Power Layer 1 "PWR-+3V3_XDS110" (solid, remove dead copper, pour order 80): 153.251,111.819 153.251,79.883 122.936,79.883 122.936,119.464 131.547,119.464 131.547,113.398 133.121,111.824
HGND_B_FB on Solid Power Layer 1 "SOLID_POWER_LAYER_1_HGND_B_FB_P068" (solid, remove dead copper, pour order 68): 48.641,45.085 48.641,22.098 76.073,22.098 76.073,45.085
HGND_A_FB on Solid Power Layer 1 "SOLID_POWER_LAYER_1_HGND_A_FB_P067" (solid, remove dead copper, pour order 67): 12.446,45.085 12.446,22.098 40.005,22.098 40.005,45.085
HGND_D_FB on Solid Power Layer 1 "SOLID_POWER_LAYER_1_HGND_D_FB_P090" (solid, remove dead copper, pour order 90): 126.111,45.085 126.111,22.098 145.451,22.098 145.436,45.085
+5V0_XDS110 on Solid Power Layer 1 "SOLID_POWER_LAYER_1_+5V0_XDS110_P082" (solid, remove dead copper, pour order 82): 131.547,133.922 123.164,133.922 123.164,119.659 131.547,119.659
HGND_C_FB on Solid Power Layer 1 "SOLID_POWER_LAYER_1_HGND_C_FB_P069" (solid, remove dead copper, pour order 69): 86.106,45.085 86.106,22.098 114.562,22.098 114.547,45.085
GND on GND/Signal Layer 2 "GND/SIGNAL_LAYER_2_GND_P065" (solid, remove dead copper, pour order 65): 153.035,44.577 11.557,44.577 11.557,61.087 26.865,61.087 26.911,98.044 153.035,98.044
no net on GND/Signal Layer 2 "Top Signal-USB_GND" (solid, remove dead copper, pour order 85): 134.167,134.694 134.167,114.672 134.516,114.324 153.956,114.324 153.956,133.637 153.882,133.637 152.825,134.694
HGND_C_FB on GND/Signal Layer 2 "GND/SIGNAL_LAYER_2_HGND_C_FB_P057" (solid, remove dead copper, pour order 57): 90.932,27.94 90.932,22.352 104.902,22.352 104.902,27.94
HGND_D_FB on GND/Signal Layer 2 "GND/SIGNAL_LAYER_2_HGND_D_FB_P091" (solid, remove dead copper, pour order 91): 125.73,28.829 125.73,21.971 138.049,21.971 138.049,28.829
HGND_B_FB on GND/Signal Layer 2 "GND/SIGNAL_LAYER_2_HGND_B_FB_P055" (solid, remove dead copper, pour order 55): 54.61,27.686 54.61,21.844 69.342,21.844 69.342,27.686
HGND_A_FB on GND/Signal Layer 2 "GND/SIGNAL_LAYER_2_HGND_A_FB_P053" (solid, remove dead copper, pour order 53): 19.558,27.813 19.558,22.352 33.909,22.352 33.909,27.813

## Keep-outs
GND/Signal 1:
  region: 95.377,56.896 95.377,64.94 92.284,67.945 87.275,67.945 86.118,64.774 86.113,56.896
Keep-Out Layer:
  lines w0.2: 152.629,134.569 cw(c152.629,133.299) 153.899,133.299 153.899,127.069

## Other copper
GND/Signal 1:
  pour cut-out: 141.478,108.92 136.003,108.92 136.003,107.849 136.223,107.849 141.478,107.849 141.478,108.9
  pour cut-out: 148.669,99.084 136.269,99.084 134.769,97.584 134.769,84.941 136.026,83.684 148.669,83.684 150.169,85.184 150.169,97.584

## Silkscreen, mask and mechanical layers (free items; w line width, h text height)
Top Overlay:
  drawing of 50 lines, arcs and shapes, not listed
  text "TIDA-010244_Rev2" at 49.022,164.084 h2
  text "+5V0" at 127.635,134.366 h0.76
  text "GND" at 113.309,128.549 h0.76
  text "GND" at 128.143,127.381 h0.76
  text "GND" at 113.309,125.882 h0.76
  text "+5V_MCU" at 110.642,122.834 h0.76
  text "VDD_3V3" at 111.531,117.881 h0.76
  text "J8" at 89.941,112.42 h0.76
  text "TDO" at 116.611,110.896 h0.76
  text "PA17" at 89.814,110.642 h0.76
  text "PA16" at 89.814,109.499 h0.76
  text "BLE_SWCLK" at 101.956,108.737 h0.76 r90
  text "MCU_TCK" at 104.75,108.737 h0.76 r90
  text "MCU_SWCLK" at 107.417,108.737 h0.76 r90
  text "TDI" at 116.611,108.737 h0.76
  text "PA15" at 89.814,108.356 h0.76
  text "PA14" at 89.814,107.213 h0.76
  text "PA13" at 89.814,105.943 h0.76
  text "RESET" at 116.357,104.673 h0.76
  text "PA12" at 89.814,104.546 h0.76
  text "BLE_SWDIO" at 105.562,103.911 h0.76
  text "RX" at 118.135,102.006 h0.76
  text "XDS110 Out" at 130.683,101.727 h0.76
  text "MCU_TMS" at 105.562,101.371 h0.76
  text "TX" at 118.008,99.212 h0.76
  text "FTDI" at 97.561,99.085 h0.76
  text "MCU_SWDIO" at 105.562,98.704 h0.76
  text "VDD" at 80.797,98.196 h0.76
  text "GND" at 97.561,97.053 h0.76
  text "BSL" at 80.797,95.656 h0.76
  text "CTS" at 97.561,94.513 h0.76
  text "MCU_RXD" at 105.816,93.624 h0.76
  text "GND" at 80.797,93.116 h0.76
  text "VDD_3V3" at 97.688,91.846 h0.76
  text "MCU_TXD" at 114.96,91.338 h0.76
  text "TXD" at 97.434,89.306 h0.76
  text "RXD" at 97.434,86.639 h0.76
  text "VDD_3V3" at 109.322,86.385 h0.76 r90
  text "GND" at 104.115,86.258 h0.76 r90
  text "GND" at 106.909,86.258 h0.76 r90
  text "PA12-17" at 88.748,84.353 h0.76 r90
  text "RTS" at 97.434,84.226 h0.76
  text "UART" at 77.089,84.074 h1.52
  text "M0 CLK" at 93.624,82.194 h0.76
  text "MCU_RX" at 64.798,80.038 h0.76
  text "BLE_TX" at 69.833,80.001 h0.76
  text "HY_RX" at 75.05,80.001 h0.76
  text "BLE_RX" at 69.889,78.515 h0.76
  text "MCU_TX" at 64.794,78.482 h0.76
  text "HY_TX" at 75.051,78.448 h0.76
  text "PWM_CLK" at 96.799,76.225 h0.76
  text "SPI_CLK" at 71.145,70.637 h0.76
  text "3V3" at 34.823,63.652 h1.52
  text "GND" at 129.946,63.398 h1.52
  text "ACT" at 100.612,63.222 h0.51 r90
  text "MSP432 TDO" at 143.129,61.243 h0.76 r90
  text "MSP432 TDI" at 145.854,61.243 h0.76 r90
  text "MSP432 SWDIO" at 148.479,59.712 h0.76 r90
  text "MSP432 SWCLK" at 150.946,59.294 h0.76 r90
  text "REACT" at 101.321,58.903 h0.51
  text "ACT" at 103.586,55.555 h0.76 r330
  text "REACT" at 93.02,54.31 h0.76 r30
  text "DOUT" at 134.264,53.873 h0.76
  text "ADC_SYNC" at 137.566,53.873 h0.76
  text "GND" at 103.332,53.015 h0.76 r330
  text "GND" at 94.163,52.786 h0.76 r30
  text "DRDY4" at 131.851,49.555 h0.76
  text "GND" at 139.725,49.428 h0.76
  text "DIN" at 123.038,48.158 h0.76 r90
  text "CS4" at 125.832,48.158 h0.76 r90
  text "SCLK4" at 128.245,46.761 h0.76 r90
  text "CS1" at 14.834,45.618 h0.76 r90
  text "CS2" at 50.902,45.364 h0.76 r90
  text "CS3" at 86.716,45.364 h0.76 r90
  text "Danger" at 142.494,45.085 h1.52
  text "ADC_CLK4" at 130.912,44.475 h0.76 r90
  text "SCLK1" at 17.374,44.094 h0.76 r90
  text "ACLK1" at 20.041,44.094 h0.76 r90
  text "DRDY1" at 22.581,44.094 h0.76 r90
  text "SCLK2" at 53.569,43.84 h0.76 r90
  text "SCLK3" at 89.256,43.84 h0.76 r90
  text "ACLK3" at 91.796,43.84 h0.76 r90
  text "ACLK2" at 56.363,43.713 h0.76 r90
  text "DRDY2" at 58.649,43.713 h0.76 r90
  text "DRDY3" at 94.336,43.713 h0.76 r90
  text "High" at 142.621,43.053 h1.52
  text "Danger" at 40.894,41.783 h1.52
  text "Danger" at 75.946,41.783 h1.52
  text "Voltage" at 142.748,40.894 h1.52
  text "Danger" at 112.522,40.64 h1.52
  text "High" at 42.037,39.751 h1.52
  text "High" at 77.089,39.751 h1.52
  text "High" at 113.665,38.608 h1.52
  text "Voltage" at 43.053,37.592 h1.52
  text "Voltage" at 78.105,37.592 h1.52
  text "Voltage" at 114.681,36.449 h1.52
  text "L2" at 72.536,15.132 h2.54
  text "L1" at 35.833,15.005 h2.54
  text "L3" at 108.604,14.497 h2.54
  text "N" at 129.432,13.862 h2.54
Bottom Overlay:
  text "J2/J4" at 117.867,83.031 h0.76 r270
M1 Board Outline:
  lines w1.2: 145.32,187.265 145.346,175.717 155.321,175.717 155.321,127.127 148.844,127.127 148.844,117.602 155.321,117.602 155.321,14.732 145.346,14.732 145.346,-0.161 ; 145.334,187.308 10.161,187.197 10.091,174.967 0.219,174.967 ccw(c0.219,174.839) 0.091,174.839 0.091,14.839 ccw(c0.219,14.839) 0.219,14.712 10.091,14.712 10.091,-0.161 ccw(c10.219,-0.161) 10.219,-0.288 145.219,-0.288 ccw(c145.219,-0.161) 145.346,-0.161
M2 Board Dimensions:
  rectangle: -0.254,-6.731 2.921,-3.556
  rectangle: 2.921,-9.906 12.446,-6.731
  lines w0.178: -0.254,-9.906 -0.254,-3.556 25.146,-3.556 25.146,-9.906 ; -0.254,-6.731 25.146,-6.731 ; 2.921,-9.906 2.921,-3.556 ; 6.096,-9.906 6.096,-3.556 ; 12.446,-9.906 12.446,-3.556 ; 18.796,-9.906 18.796,-3.556
M5 Assembly Top:
  text "COMPONENTS MARKED 'DNP' SHOULD NOT BE POPULATED." at 29.045,-7.836 h0.76
M6 Assembly Bottom:
  text "COMPONENTS MARKED 'DNP' SHOULD NOT BE POPULATED." at 154.737,-7.823 h0.76
M9 Title Sheet:
  drawing of 53 lines, arcs and shapes, not listed
  text "1" at 18.538,204.381 h0.76
  text "2" at 81.928,204.381 h0.76
  text "3" at 145.157,204.381 h0.76
  text "4" at 208.826,204.381 h0.76
  text "5" at 272.301,204.381 h0.76
  text "6" at 335.928,204.381 h0.76
  text "A" at -10.833,175.349 h0.76
  text "A" at 365.087,175.349 h0.76
  text "B" at -10.833,114.897 h0.76
  text "B" at 365.087,114.897 h0.76
  text "C" at -10.833,54.572 h0.76
  text "C" at 365.087,54.572 h0.76
  text "PROJECT TITLE:" at 287.871,7.302 h0.76
  text ".PRJ_Title" at 289.141,3.916 h0.76
  text "DESIGNED FOR:" at 287.871,-0.343 h0.76
  text ".PRJ_Customer" at 289.141,-3.899 h0.76
  text "D" at -10.833,-5.626 h0.76
  text "D" at 365.087,-5.626 h0.76
  text "FILE NAME:" at 287.871,-7.963 h0.76
  text ".PCB_File_Name_No_Path" at 289.141,-11.011 h0.76
  text "Texas Instruments (TI) and/or its licensors do not warrant the accuracy or completeness of this specification" at 161.646,-15.122 h0.76
  text "ENGINEER:" at 287.871,-15.329 h0.76
  text "LAYOUT BY:" at 326.098,-15.329 h0.76
  text "or any information contained therein. TI and/or its licensors do not warrant that this design will meet" at 160.503,-17.983 h0.76
  text ".PRJ_Engineer" at 289.141,-19.266 h0.76
  text ".PCB_Layout" at 327.381,-19.266 h0.76
  text "the specifications, will be suitable for your application or fit for any particular purpose, or will operate in" at 160.503,-20.845 h0.76
  text ".Layer_Name" at 14.402,-21.552 h0.76
  text "ALTIUM DESIGNER VERSION:" at 326.098,-23.203 h0.76
  text "an implementation. TI and/or its licensors do not warrant that the design is production worthy. You should" at 160.503,-23.707 h0.76
  text "completely validate and test your design implementation to confirm the system functionality for your application." at 161.646,-26.568 h0.76
  text ".print_Scale" at 289.141,-26.589 h0.76
  text ".Application_BuildNumber" at 327.381,-26.589 h0.76
  text "1" at 18.538,-31.839 h0.76
  text "2" at 81.928,-31.839 h0.76
  text "4" at 208.826,-31.839 h0.76
  text "5" at 272.301,-31.839 h0.76
  text "6" at 335.928,-31.839 h0.76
